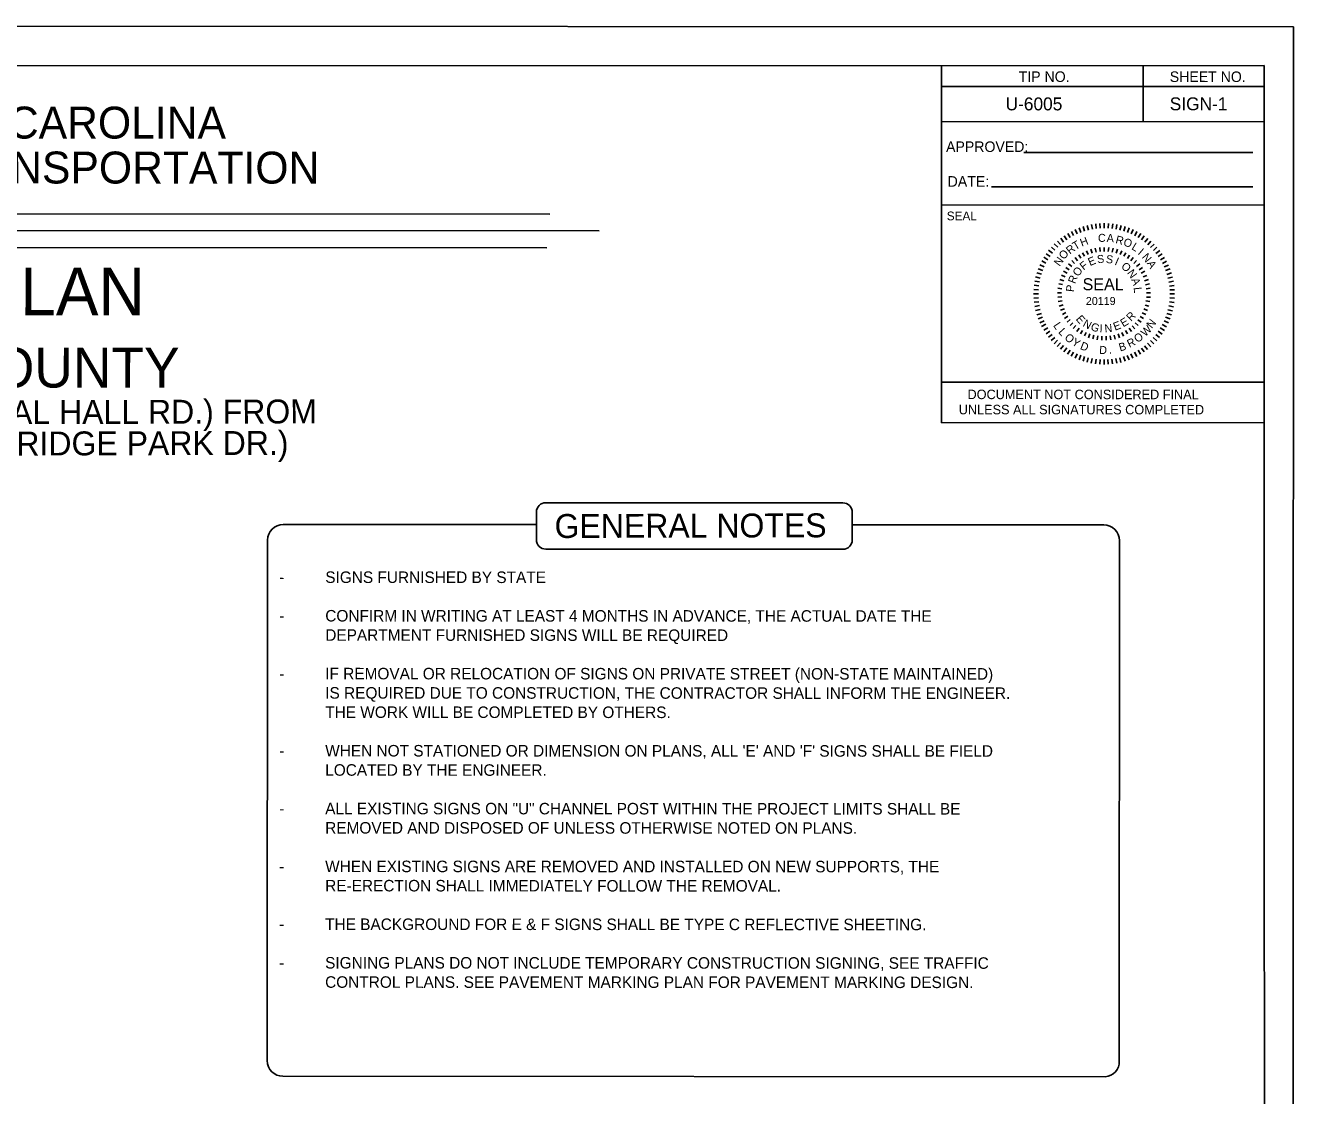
# Model space of a CAD drawing. Extents: x 50703 to 52785, y 49383 to 50479.
# Drawn here: x 51651 to 52386, y 49859 to 50479 of the extents above; entities that cross this region are included whole.
import ezdxf

# ---------------------------------------------------------------- set-up
doc = ezdxf.new("R2010")
doc.units = 0
for name, color, linetype in [('Default', 7, 'Continuous'), ('Old_Level_10', 7, 'Continuous'), ('Old_Level_18', 7, 'Continuous'), ('Old_Level_4', 7, 'Continuous'), ('Sheet Plot Border Outside CELL', 7, 'Continuous'), ('Sheet Sticker Exception Certification CELL', 7, 'Continuous'), ('Sheet Title CELL', 7, 'Continuous')]:
    doc.layers.add(name, color=color, linetype=linetype)

msp = doc.modelspace()

# ---------------------------------------------------------------- linework, layer by layer
at = {"layer": 'Default'}
for p, q in [((52264.1, 50362.73), (52264.92, 50360.06)), ((52266.48, 50363.38), (52267.14, 50360.68)), ((52268.9, 50363.9), (52269.39, 50361.16)), ((52271.34, 50364.26), (52271.67, 50361.5)), ((52273.79, 50364.48), (52273.96, 50361.7)), ((52276.26, 50364.56), (52276.26, 50361.77)), ((52278.73, 50364.48), (52278.56, 50361.7)), ((52281.19, 50364.25), (52280.85, 50361.49)), ((52283.63, 50363.88), (52283.13, 50361.14)), ((52286.04, 50363.36), (52285.38, 50360.65)), ((52288.42, 50362.69), (52287.59, 50360.03)), ((52251.05, 50355.89), (52252.76, 50353.7)), ((52253.03, 50357.35), (52254.61, 50355.06)), ((52255.11, 50358.69), (52256.55, 50356.31)), ((52257.26, 50359.9), (52258.55, 50357.43)), ((52259.49, 50360.98), (52260.62, 50358.44)), ((52261.77, 50361.92), (52262.75, 50359.31)), ((52290.75, 50361.88), (52289.76, 50359.28)), ((52293.03, 50360.93), (52291.89, 50358.39)), ((52295.25, 50359.85), (52293.95, 50357.38)), ((52297.4, 50358.63), (52295.96, 50356.25)), ((52299.47, 50357.29), (52297.89, 50355)), ((52301.46, 50355.82), (52299.74, 50353.63)), ((52244.07, 50348.93), (52246.26, 50347.21)), ((52245.65, 50350.83), (52247.73, 50348.98)), ((52247.35, 50352.62), (52249.31, 50350.65)), ((52249.14, 50354.31), (52250.99, 50352.23)), ((52263.72, 50347.55), (52264.79, 50345.5)), ((52266.08, 50348.65), (52266.95, 50346.49)), ((52268.54, 50349.51), (52269.2, 50347.28)), ((52271.07, 50350.13), (52271.51, 50347.85)), ((52273.64, 50350.5), (52273.86, 50348.19)), ((52276.25, 50350.62), (52276.24, 50348.3)), ((52276.24, 50348.3), (52276.25, 50350.62)), ((52278.85, 50350.49), (52278.62, 50348.18)), ((52281.42, 50350.11), (52280.97, 50347.83)), ((52283.95, 50349.49), (52283.28, 50347.26)), ((52286.4, 50348.62), (52285.52, 50346.47)), ((52288.76, 50347.52), (52287.68, 50345.46)), ((52303.36, 50354.24), (52301.51, 50352.16)), ((52305.15, 50352.54), (52303.18, 50350.58)), ((52306.84, 50350.75), (52304.75, 50348.9)), ((52308.42, 50348.84), (52306.22, 50347.13)), ((52238.96, 50340.51), (52241.5, 50339.36)), ((52240.04, 50342.73), (52242.51, 50341.43)), ((52241.26, 50344.88), (52243.64, 50343.43)), ((52242.6, 50346.95), (52244.89, 50345.36)), ((52255.64, 50341.08), (52257.41, 50339.58)), ((52257.42, 50342.99), (52259.04, 50341.32)), ((52259.37, 50344.71), (52260.82, 50342.89)), ((52261.47, 50346.24), (52262.74, 50344.29)), ((52291, 50346.2), (52289.73, 50344.25)), ((52293.11, 50344.66), (52291.65, 50342.85)), ((52295.05, 50342.93), (52293.43, 50341.27)), ((52296.82, 50341.03), (52295.05, 50339.53)), ((52309.88, 50346.86), (52307.59, 50345.28)), ((52311.22, 50344.78), (52308.83, 50343.34)), ((52312.43, 50342.63), (52309.96, 50341.33)), ((52313.5, 50340.4), (52310.96, 50339.27)), ((52236.53, 50333.52), (52239.24, 50332.85)), ((52237.2, 50335.9), (52239.86, 50335.07)), ((52238.01, 50338.23), (52240.61, 50337.24)), ((52251.52, 50334.47), (52253.65, 50333.54)), ((52252.68, 50336.81), (52254.71, 50335.67)), ((52254.06, 50339.02), (52255.96, 50337.69)), ((52298.4, 50338.96), (52296.49, 50337.64)), ((52299.77, 50336.74), (52297.74, 50335.61)), ((52300.92, 50334.41), (52298.79, 50333.48)), ((52314.45, 50338.12), (52311.84, 50337.14)), ((52315.25, 50335.79), (52312.59, 50334.96)), ((52315.91, 50333.41), (52313.2, 50332.75)), ((52235.41, 50326.21), (52238.19, 50326.04)), ((52235.64, 50328.67), (52238.4, 50328.33)), ((52236.01, 50331.1), (52238.75, 50330.6)), ((52249.47, 50326.97), (52251.77, 50326.69)), ((52249.91, 50329.53), (52252.18, 50329.03)), ((52250.6, 50332.04), (52252.81, 50331.32)), ((52301.84, 50331.97), (52299.63, 50331.26)), ((52302.52, 50329.46), (52300.25, 50328.96)), ((52302.96, 50326.89), (52300.65, 50326.62)), ((52316.43, 50330.99), (52313.68, 50330.5)), ((52316.79, 50328.55), (52314.03, 50328.22)), ((52317.01, 50326.09), (52314.23, 50325.93)), ((52235.33, 50323.74), (52238.12, 50323.73)), ((52235.4, 50321.27), (52238.18, 50321.43)), ((52235.63, 50318.81), (52238.39, 50319.14)), ((52249.28, 50324.37), (52251.59, 50324.31)), ((52249.33, 50321.77), (52251.65, 50321.93)), ((52249.65, 50319.18), (52251.93, 50319.57)), ((52300.48, 50319.58), (52302.77, 50319.19)), ((52303.07, 50321.69), (52300.76, 50321.86)), ((52303.14, 50324.29), (52300.82, 50324.24)), ((52316.78, 50318.7), (52314.01, 50319.04)), ((52317, 50321.16), (52314.22, 50321.33)), ((52317.08, 50323.62), (52314.3, 50323.63)), ((52235.99, 50316.37), (52238.73, 50316.87)), ((52236.51, 50313.96), (52239.21, 50314.62)), ((52237.16, 50311.57), (52239.83, 50312.4)), ((52250.2, 50316.64), (52252.44, 50317.24)), ((52251.01, 50314.16), (52253.18, 50314.98)), ((52252.04, 50311.78), (52254.12, 50312.8)), ((52253.3, 50309.5), (52255.28, 50310.72)), ((52299.07, 50309.44), (52297.1, 50310.66)), ((52300.34, 50311.71), (52298.26, 50312.74)), ((52301.38, 50314.09), (52299.21, 50314.92)), ((52302.19, 50316.57), (52299.95, 50317.18)), ((52315.22, 50311.46), (52312.55, 50312.3)), ((52315.88, 50313.85), (52313.18, 50314.51)), ((52316.4, 50316.26), (52313.67, 50316.76)), ((52237.97, 50309.24), (52240.58, 50310.23)), ((52238.91, 50306.96), (52241.45, 50308.1)), ((52239.99, 50304.74), (52242.46, 50306.03)), ((52241.2, 50302.58), (52243.58, 50304.02)), ((52254.78, 50307.35), (52256.63, 50308.76)), ((52256.46, 50305.36), (52258.16, 50306.94)), ((52258.31, 50303.54), (52259.86, 50305.28)), ((52260.34, 50301.91), (52261.71, 50303.79)), ((52292.01, 50301.87), (52290.65, 50303.74)), ((52294.05, 50303.49), (52292.51, 50305.23)), ((52295.91, 50305.31), (52294.21, 50306.89)), ((52297.59, 50307.29), (52295.75, 50308.71)), ((52311.16, 50302.48), (52308.78, 50303.93)), ((52312.38, 50304.64), (52309.91, 50305.93)), ((52313.46, 50306.86), (52310.92, 50308)), ((52314.41, 50309.13), (52311.8, 50310.13)), ((52242.54, 50300.51), (52244.83, 50302.09)), ((52244, 50298.52), (52246.19, 50300.23)), ((52245.58, 50296.62), (52247.66, 50298.46)), ((52247.27, 50294.82), (52249.24, 50296.79)), ((52262.52, 50300.48), (52263.7, 50302.48)), ((52264.82, 50299.27), (52265.8, 50301.37)), ((52267.23, 50298.28), (52268.01, 50300.47)), ((52270.27, 50299.79), (52269.71, 50297.53)), ((52272.28, 50297.03), (52272.62, 50299.33)), ((52274.87, 50296.77), (52274.98, 50299.09)), ((52277.47, 50296.77), (52277.36, 50299.09)), ((52280.06, 50297.02), (52279.73, 50299.32)), ((52282.62, 50297.52), (52282.06, 50299.77)), ((52285.11, 50298.26), (52284.34, 50300.45)), ((52287.52, 50299.24), (52286.55, 50301.34)), ((52289.83, 50300.44), (52288.66, 50302.45)), ((52305.07, 50294.74), (52303.1, 50296.71)), ((52306.76, 50296.53), (52304.68, 50298.38)), ((52308.35, 50298.43), (52306.16, 50300.15)), ((52309.81, 50300.41), (52307.53, 50302)), ((52249.06, 50293.12), (52250.91, 50295.21)), ((52250.96, 50291.54), (52252.67, 50293.73)), ((52252.94, 50290.07), (52254.53, 50292.36)), ((52255.01, 50288.73), (52256.46, 50291.11)), ((52257.16, 50287.51), (52258.46, 50289.98)), ((52259.38, 50286.43), (52260.53, 50288.97)), ((52292.93, 50286.39), (52291.79, 50288.93)), ((52295.15, 50287.46), (52293.86, 50289.93)), ((52297.31, 50288.67), (52295.87, 50291.06)), ((52299.38, 50290.01), (52297.8, 50292.3)), ((52301.37, 50291.47), (52299.66, 50293.66)), ((52303.27, 50293.05), (52301.43, 50295.14)), ((52261.66, 50285.48), (52262.65, 50288.09)), ((52263.99, 50284.67), (52264.82, 50287.34)), ((52266.37, 50284.01), (52267.04, 50286.71)), ((52268.78, 50283.48), (52269.29, 50286.22)), ((52271.22, 50283.11), (52271.56, 50285.88)), ((52273.68, 50282.88), (52273.85, 50285.66)), ((52276.15, 50282.81), (52276.15, 50285.59)), ((52278.62, 50282.88), (52278.46, 50285.66)), ((52281.08, 50283.1), (52280.75, 50285.86)), ((52283.52, 50283.46), (52283.02, 50286.2)), ((52285.93, 50283.98), (52285.27, 50286.68)), ((52288.32, 50284.64), (52287.49, 50287.3)), ((52290.65, 50285.44), (52289.66, 50288.05))]:
    msp.add_line(p, q, dxfattribs=at)
for points in [[(51261.15, 50370.27), (51954.95, 50369.95)], [(51229.19, 50360.53), (51983.6, 50360.18)], [(51259.46, 50350.77), (51953.26, 50350.44)]]:
    msp.add_lwpolyline(points, dxfattribs=at)
at = {"layer": 'Old_Level_10'}
for p, q in [((52298.79, 50423.48), (52298.81, 50456.02)), ((52298.8, 50431.06), (52298.81, 50456.02)), ((52369.04, 50455.98), (52369.04, 50455.98)), ((52182.05, 50443.86), (52298.8, 50443.8)), ((52298.8, 50443.8), (52369.04, 50443.76)), ((52182.04, 50423.55), (52369.03, 50423.44)), ((52229.72, 50405.64), (52362.34, 50405.58)), ((52211.03, 50385.74), (52362.33, 50385.67))]:
    msp.add_line(p, q, dxfattribs=at)
at = {"layer": 'Old_Level_18'}
msp.add_lwpolyline([(52369.04, 50455.98), (50869.05, 50455.87), (50869.12, 49405.87), (52369.12, 49405.98)], close=True, dxfattribs=at)
at = {"layer": 'Sheet Plot Border Outside CELL'}
msp.add_lwpolyline([(52386.04, 50478.48), (50703.13, 50479.27), (50702.62, 49383.36), (52385.53, 49382.58)], close=True, dxfattribs=at)
at = {"layer": 'Sheet Sticker Exception Certification CELL'}
msp.add_lwpolyline([(52181.97, 50272.54), (52368.96, 50272.46), (52368.95, 50248.96), (52181.96, 50249.05)], close=True, dxfattribs=at)
at = {"layer": 'Sheet Title CELL'}
for p, q in [((52182.04, 50431.12), (52182.06, 50456.07)), ((52182.02, 50383.94), (52182.04, 50431.12)), ((52181.97, 50272.54), (52182.02, 50383.94)), ((52182.02, 50375.2), (52369.01, 50375.11)), ((52368.96, 50272.46), (52181.97, 50272.54)), ((51947.2, 50181.21), (51947.2, 50197.23)), ((52130.23, 50181.12), (52130.24, 50197.15)), ((51800.48, 50190.07), (51947.2, 50190)), ((52130.23, 50189.92), (52276.02, 50189.85)), ((51791.25, 49879.37), (51791.39, 50180.98)), ((52284.97, 49879.14), (52285.11, 50180.76)), ((51800.34, 49870.28), (52276.8, 49870.06))]:
    msp.add_line(p, q, dxfattribs=at)
for points in [[(51952.66, 50202.68), (52124.79, 50202.6)], [(51952.65, 50175.75), (52124.77, 50175.67)]]:
    msp.add_lwpolyline(points, dxfattribs=at)
for centre, radius, start, end in [((51952.66, 50197.23), 5.45, 89.97341, 179.97341), ((52124.78, 50197.15), 5.45, 359.97341, 89.97341), ((51800.48, 50180.98), 9.09, 89.97341, 179.97341), ((52276.02, 50180.76), 9.09, 359.97341, 89.97341), ((51952.65, 50181.21), 5.45, 179.97341, 269.97341), ((52124.78, 50181.13), 5.45, 269.97341, 359.97341), ((51800.34, 49879.37), 9.09, 179.97341, 269.97341), ((52276.34, 49878.68), 8.64, 273.04586, 3.04586)]:
    msp.add_arc(centre, radius, start, end, dxfattribs=at)

# ---------------------------------------------------------------- texts
at = {"layer": 'Default'}
for s, height, rotation, p in [('STATE OF NORTH CAROLINA', 18.4936, 359.97341, (51418.32, 50413.79)), ('DEPARTMENT OF TRANSPORTATION', 18.4936, 359.97341, (51374.88, 50387.78)), ('T', 4.64, 30.41999, (52259.56, 50348.94)), ('H', 4.64, 20.98805, (52263.3, 50350.96)), ('C', 4.64, 357.27736, (52272.54, 50353.92)), ('A', 4.64, 357.27736, (52277.61, 50353.82)), ('R', 4.64, 345.26805, (52282.52, 50353.13)), ('O', 4.64, 342.21124, (52287.02, 50351.79)), ('O', 4.64, 51.63769, (52253.07, 50343.23)), ('R', 4.64, 38.58096, (52256.44, 50346.35)), ('L', 4.64, 329.07495, (52291.73, 50349.72)), ('I', 4.64, 319.49948, (52295.47, 50347.02)), ('N', 4.64, 310.20502, (52297.79, 50344.83)), ('N', 4.64, 53.59712, (52250.4, 50339.31)), ('F', 4.64, 38.16101, (52264.33, 50337.12)), ('E', 4.64, 22.86476, (52268.04, 50339.74)), ('S', 4.64, 7.56852, (52272.4, 50341.33)), ('S', 4.64, 352.27227, (52277.04, 50341.71)), ('I', 4.64, 336.97602, (52281.97, 50340.7)), ('O', 4.64, 321.67978, (52285.71, 50338.89)), ('A', 4.64, 300.43749, (52300.85, 50341.4)), ('SIGNING PLAN', 27.7403, 359.97341, (51456.39, 50311.3)), ('R', 4.64, 68.7535, (52259.4, 50329.22)), ('O', 4.64, 53.45725, (52261.24, 50333.38)), ('SEAL', 6.965, 359.92039, (52263.73, 50325.79)), ('N', 4.64, 306.38353, (52289.28, 50335.77)), ('P', 4.64, 84.04975, (52258.69, 50324.62)), ('A', 4.64, 291.08729, (52291.82, 50331.97)), ('L', 4.64, 275.79104, (52293.31, 50327.38)), ('20119', 4.64, 359.92039, (52265.62, 50317.25)), ('E', 4.64, 309.99048, (52259.56, 50308.97)), ('R', 4.64, 44.48528, (52291.73, 50307.49)), ('L', 4.64, 303.85541, (52246.51, 50305.35)), ('L', 4.64, 311.92722, (52249.38, 50301.36)), ('N', 4.64, 330.84556, (52263.45, 50305.1)), ('G', 4.64, 339.61179, (52267.99, 50302.91)), ('I', 4.64, 357.70659, (52273.51, 50301.42)), ('N', 4.64, 5.33625, (52276.66, 50301.26)), ('E', 4.64, 20.72832, (52282.54, 50302.29)), ('E', 4.64, 30.7142, (52287.3, 50304.26)), ('W', 4.64, 43.24482, (52300.04, 50298.62)), ('N', 4.64, 52.12745, (52303.94, 50303.28)), ('O', 4.64, 320.56997, (52252.9, 50297.7)), ('Y', 4.64, 329.24256, (52257.11, 50294.46)), ('D', 4.64, 338.21504, (52261.94, 50291.83)), ('R', 4.64, 25.53957, (52290.86, 50292.38)), ('O', 4.64, 34.36219, (52295.47, 50295.14)), ('FORSYTH COUNTY', 23.1165, 359.97341, (51453.61, 50269.48)), ('D', 4.64, 356.01035, (52273.22, 50288.99)), ('.', 4.64, 3.75269, (52279.07, 50288.94)), ('B', 4.64, 16.53701, (52285.5, 50290.27)), ('LOCATION: NC 65 (BETHANIA RURAL HALL RD.) FROM', 13.8702, 0.15565, (51335.63, 50247.33)), ('ANGUS ST. TO SR 3983 (NORTHRIDGE PARK DR.)', 13.8702, 0.15565, (51360.38, 50229.21)), ('GENERAL NOTES', 13.8661, 0.15565, (51957.75, 50182.21)), ('-', 6.67, 359.97341, (51798.18, 50156.18)), ('SIGNS FURNISHED BY STATE', 6.6709, 359.97341, (51824.86, 50156.17)), ('-', 6.67, 359.97341, (51798.17, 50133.84)), ('CONFIRM IN WRITING AT LEAST 4 MONTHS IN ADVANCE, THE ACTUAL DATE THE', 6.6709, 359.97341, (51824.85, 50133.83)), ('DEPARTMENT FURNISHED SIGNS WILL BE REQUIRED', 6.6709, 359.97341, (51824.85, 50122.66)), ('IF REMOVAL OR RELOCATION OF SIGNS ON PRIVATE STREET (NON-STATE MAINTAINED)', 6.6709, 359.97341, (51824.84, 50100.32)), ('-', 6.67, 359.97341, (51798.16, 50100.33)), ('IS REQUIRED DUE TO CONSTRUCTION, THE CONTRACTOR SHALL INFORM THE ENGINEER.', 6.6709, 359.97341, (51824.83, 50089.14)), ('THE WORK WILL BE COMPLETED BY OTHERS.', 6.6709, 359.97341, (51824.83, 50077.97)), ("WHEN NOT STATIONED OR DIMENSION ON PLANS, ALL 'E' AND 'F' SIGNS SHALL BE FIELD", 6.6709, 359.97341, (51824.82, 50055.63)), ('-', 6.67, 359.97341, (51798.13, 50055.64)), ('LOCATED BY THE ENGINEER.', 6.6709, 359.97341, (51824.81, 50044.46)), ('-', 6.67, 359.97341, (51798.12, 50022.13)), ('ALL EXISTING SIGNS ON "U" CHANNEL POST WITHIN THE PROJECT LIMITS SHALL BE', 6.6709, 359.97341, (51824.8, 50022.12)), ('REMOVED AND DISPOSED OF UNLESS OTHERWISE NOTED ON PLANS.', 6.6709, 359.97341, (51824.8, 50010.95)), ('WHEN EXISTING SIGNS ARE REMOVED AND INSTALLED ON NEW SUPPORTS, THE', 6.6709, 359.97341, (51824.79, 49988.61)), ('-', 6.67, 359.97341, (51798.1, 49988.62)), ('RE-ERECTION SHALL IMMEDIATELY FOLLOW THE REMOVAL.', 6.6709, 359.97341, (51824.78, 49977.44)), ('-', 6.67, 359.97341, (51798.09, 49955.11)), ('THE BACKGROUND FOR E & F SIGNS SHALL BE TYPE C REFLECTIVE SHEETING.', 6.6709, 359.97341, (51824.77, 49955.09)), ('SIGNING PLANS DO NOT INCLUDE TEMPORARY CONSTRUCTION SIGNING, SEE TRAFFIC', 6.6709, 359.97341, (51824.76, 49932.75)), ('-', 6.67, 359.97341, (51798.08, 49932.76)), ('CONTROL PLANS. SEE PAVEMENT MARKING PLAN FOR PAVEMENT MARKING DESIGN.', 6.6709, 359.97341, (51824.76, 49921.58))]:
    msp.add_text(s, height=height, rotation=rotation, dxfattribs=at).set_placement(p)
at = {"layer": 'Old_Level_10'}
for s, height, p in [('TIP NO.', 6.11, (52226.7, 50446.51)), ('SHEET NO.', 6.11, (52314.26, 50446.46)), ('SEAL', 5.094, (52185.04, 50366.29))]:
    msp.add_text(s, height=height, rotation=359.96835, dxfattribs=at).set_placement(p)
at = {"layer": 'Old_Level_4'}
for s, p in [('APPROVED:', (52184.62, 50405.93)), ('DATE:', (52185.53, 50385.79))]:
    msp.add_text(s, height=6.11, rotation=359.96835, dxfattribs=at).set_placement(p)
at = {"layer": 'Sheet Sticker Exception Certification CELL'}
for s, p in [('DOCUMENT NOT CONSIDERED FINAL', (52197.04, 50262.69)), ('UNLESS ALL SIGNATURES COMPLETED', (52191.97, 50253.89))]:
    msp.add_text(s, height=5.4984, rotation=359.97341, dxfattribs=at).set_placement(p)
at = {"layer": 'Sheet Title CELL'}
for s, p in [('U-6005', (52219.11, 50430.02)), ('SIGN-1', (52314.25, 50430.05))]:
    msp.add_text(s, height=7.5, rotation=359.96835, dxfattribs=at).set_placement(p)

doc.saveas('drawing.dxf')
